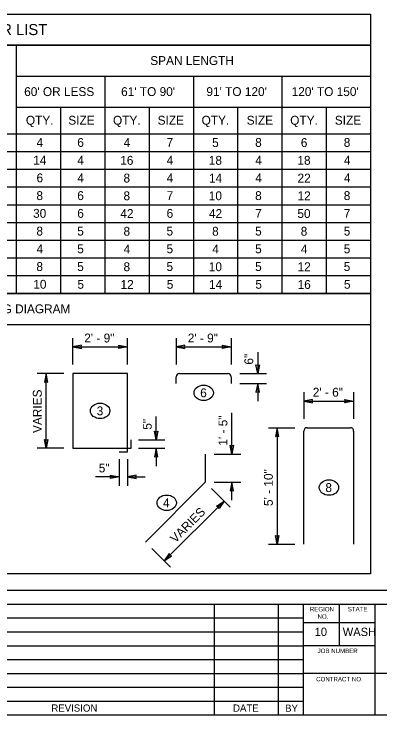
# Model space of a CAD drawing. Extents: x 99862 to 103151, y 100000 to 102076.
# Drawn here: x 100566 to 101227, y 100000 to 101265 of the extents above; entities that cross this region are included whole.
import ezdxf

# ---------------------------------------------------------------- set-up
doc = ezdxf.new("R2010")
doc.units = 0
for name, color, linetype in [('Level 10', 7, 'Continuous'), ('Level 15', 7, 'Continuous'), ('Level 20', 7, 'Continuous'), ('Level 40', 7, 'Continuous'), ('Level 60', 7, 'Continuous')]:
    doc.layers.add(name, color=color, linetype=linetype)

msp = doc.modelspace()

# ---------------------------------------------------------------- linework, layer by layer
at = {"layer": 'Level 10'}
for p, q in [((100864.8, 100616.2), (100951.8, 100616.2)), ((100864.8, 100616.2), (100951.8, 100616.2)), ((100858.8, 100598.2), (100858.8, 100610.2)), ((100858.8, 100598.2), (100858.8, 100610.2)), ((100957.8, 100610.2), (100957.8, 100598.2)), ((100957.8, 100610.2), (100957.8, 100598.2)), ((101095.1, 100518.4), (101173.1, 100518.4)), ((101089.1, 100308.4), (101089.1, 100512.4)), ((101179.1, 100512.4), (101179.1, 100308.4)), ((100911.1, 100470.9), (100911.1, 100419.9)), ((100911.1, 100470.9), (100911.1, 100419.9)), ((100911.1, 100419.9), (100803.1, 100311.9)), ((100911.1, 100419.9), (100803.1, 100311.9))]:
    msp.add_line(p, q, dxfattribs=at)
for points in [[(100770.8, 100474.7), (100770.8, 100616.2), (100671.8, 100616.2), (100671.8, 100481.2), (100777.4, 100481.2)], [(100770.8, 100474.7), (100770.8, 100616.2), (100671.8, 100616.2), (100671.8, 100481.2), (100777.4, 100481.2)], [(100777.4, 100481.2), (100777.4, 100496.2)], [(100777.4, 100481.2), (100777.4, 100496.2)], [(100755.8, 100474.7), (100770.8, 100474.7)], [(100755.8, 100474.7), (100770.8, 100474.7)]]:
    msp.add_lwpolyline(points, dxfattribs=at)
for centre, start, end in [((100864.8, 100610.2), 90, 180), ((100864.8, 100610.2), 90, 180), ((100951.8, 100610.2), 0, 90), ((100951.8, 100610.2), 0, 90), ((101095.1, 100512.4), 90, 180), ((101173.1, 100512.4), 0, 90)]:
    msp.add_arc(centre, 6, start, end, dxfattribs=at)
at = {"layer": 'Level 15'}
for p, q in [((100671.8, 100632.2), (100671.8, 100680.2)), ((100671.8, 100632.2), (100671.8, 100680.2)), ((100770.8, 100632.2), (100770.8, 100680.2)), ((100770.8, 100632.2), (100770.8, 100680.2)), ((100858.8, 100680.2), (100858.8, 100632.2)), ((100858.8, 100680.2), (100858.8, 100632.2)), ((100957.8, 100680.2), (100957.8, 100632.2)), ((100957.8, 100680.2), (100957.8, 100632.2)), ((100671.8, 100664.2), (100770.8, 100664.2)), ((100671.8, 100664.2), (100770.8, 100664.2)), ((100858.8, 100664.2), (100957.8, 100664.2)), ((100858.8, 100664.2), (100957.8, 100664.2)), ((101005.8, 100654.6), (101005.8, 100616.2)), ((101005.8, 100654.6), (101005.8, 100616.2)), ((100655.8, 100616.2), (100607.8, 100616.2)), ((100655.8, 100616.2), (100607.8, 100616.2)), ((100623.8, 100481.2), (100623.8, 100616.2)), ((100623.8, 100481.2), (100623.8, 100616.2)), ((100973.8, 100616.2), (101021.8, 100616.2)), ((100973.8, 100616.2), (101021.8, 100616.2)), ((100973.8, 100598.2), (101021.8, 100598.2)), ((100973.8, 100598.2), (101021.8, 100598.2)), ((101005.8, 100598.2), (101005.8, 100566.2)), ((101005.8, 100598.2), (101005.8, 100566.2)), ((101089.1, 100582.4), (101089.1, 100534.4)), ((101089.1, 100582.4), (101089.1, 100534.4)), ((101179.1, 100582.4), (101179.1, 100534.4)), ((101179.1, 100582.4), (101179.1, 100534.4)), ((101089.1, 100566.4), (101179.1, 100566.4)), ((101089.1, 100566.4), (101179.1, 100566.4)), ((100959.1, 100470.9), (100959.1, 100545.3)), ((100959.1, 100470.9), (100959.1, 100545.3)), ((100822.4, 100496.2), (100822.4, 100538.3)), ((100822.4, 100496.2), (100822.4, 100538.3)), ((101025.1, 100518.4), (101073.1, 100518.4)), ((101025.1, 100518.4), (101073.1, 100518.4)), ((101041.1, 100518.4), (101041.1, 100308.4)), ((100790.4, 100496.2), (100838.4, 100496.2)), ((100790.4, 100496.2), (100838.4, 100496.2)), ((100655.8, 100481.2), (100607.8, 100481.2)), ((100655.8, 100481.2), (100607.8, 100481.2)), ((100790.4, 100481.2), (100838.4, 100481.2)), ((100790.4, 100481.2), (100838.4, 100481.2)), ((100822.4, 100481.2), (100822.4, 100449.2)), ((100822.4, 100481.2), (100822.4, 100449.2)), ((100927.1, 100470.9), (100975.1, 100470.9)), ((100927.1, 100470.9), (100975.1, 100470.9)), ((100755.8, 100461.7), (100755.8, 100413.7)), ((100755.8, 100461.7), (100755.8, 100413.7)), ((100770.8, 100461.7), (100770.8, 100413.7)), ((100770.8, 100461.7), (100770.8, 100413.7)), ((100755.8, 100429.7), (100713.2, 100429.7)), ((100755.8, 100429.7), (100713.2, 100429.7)), ((100770.8, 100429.7), (100802.8, 100429.7)), ((100770.8, 100429.7), (100802.8, 100429.7)), ((100927.1, 100419.9), (100975.1, 100419.9)), ((100927.1, 100419.9), (100975.1, 100419.9)), ((100959.1, 100387.9), (100959.1, 100419.9)), ((100959.1, 100387.9), (100959.1, 100419.9)), ((100922.4, 100408.6), (100956.3, 100374.7)), ((100922.4, 100408.6), (100956.3, 100374.7)), ((100945, 100386), (100837, 100278)), ((100814.4, 100300.6), (100848.3, 100266.6)), ((100814.4, 100300.6), (100848.3, 100266.6)), ((101025.1, 100308.4), (101073.1, 100308.4)), ((101025.1, 100308.4), (101073.1, 100308.4))]:
    msp.add_line(p, q, dxfattribs=at)
for points in [[(100671.8, 100664.2), (100687.6, 100661.1), (100686.8, 100664.2), (100687.6, 100667.3)], [(100671.8, 100664.2), (100687.6, 100661.1), (100686.8, 100664.2), (100687.6, 100667.3)], [(100770.8, 100664.2), (100755.1, 100661.1), (100755.8, 100664.2), (100755.1, 100667.3)], [(100770.8, 100664.2), (100755.1, 100661.1), (100755.8, 100664.2), (100755.1, 100667.3)], [(100858.8, 100664.2), (100874.5, 100661.1), (100873.8, 100664.2), (100874.5, 100667.3)], [(100858.8, 100664.2), (100874.5, 100661.1), (100873.8, 100664.2), (100874.5, 100667.3)], [(100957.8, 100664.2), (100942.1, 100661.1), (100942.8, 100664.2), (100942.1, 100667.3)], [(100957.8, 100664.2), (100942.1, 100661.1), (100942.8, 100664.2), (100942.1, 100667.3)], [(101005.8, 100616.2), (101002.7, 100631.9), (101005.8, 100631.2), (101008.9, 100631.9)], [(101005.8, 100616.2), (101002.7, 100631.9), (101005.8, 100631.2), (101008.9, 100631.9)], [(100623.8, 100616.2), (100620.8, 100600.5), (100623.8, 100601.2), (100626.9, 100600.5)], [(100623.8, 100616.2), (100620.8, 100600.5), (100623.8, 100601.2), (100626.9, 100600.5)], [(101005.8, 100598.2), (101002.7, 100582.5), (101005.8, 100583.2), (101008.9, 100582.5)], [(101005.8, 100598.2), (101002.7, 100582.5), (101005.8, 100583.2), (101008.9, 100582.5)], [(101089.1, 100566.4), (101104.8, 100563.3), (101104.1, 100566.4), (101104.8, 100569.5)], [(101089.1, 100566.4), (101104.8, 100563.3), (101104.1, 100566.4), (101104.8, 100569.5)], [(101179.1, 100566.4), (101163.4, 100563.3), (101164.1, 100566.4), (101163.4, 100569.5)], [(101179.1, 100566.4), (101163.4, 100563.3), (101164.1, 100566.4), (101163.4, 100569.5)], [(101041.1, 100518.4), (101038, 100502.6), (101041.1, 100503.4), (101044.2, 100502.6)], [(101041.1, 100518.4), (101038, 100502.6), (101041.1, 100503.4), (101044.2, 100502.6)], [(100822.4, 100496.2), (100819.3, 100511.9), (100822.4, 100511.2), (100825.5, 100511.9)], [(100822.4, 100496.2), (100819.3, 100511.9), (100822.4, 100511.2), (100825.5, 100511.9)], [(100623.8, 100481.2), (100620.8, 100496.9), (100623.8, 100496.2), (100626.9, 100496.9)], [(100623.8, 100481.2), (100620.8, 100496.9), (100623.8, 100496.2), (100626.9, 100496.9)], [(100822.4, 100481.2), (100819.3, 100465.5), (100822.4, 100466.2), (100825.5, 100465.5)], [(100822.4, 100481.2), (100819.3, 100465.5), (100822.4, 100466.2), (100825.5, 100465.5)], [(100959.1, 100470.9), (100956, 100486.6), (100959.1, 100485.9), (100962.2, 100486.6)], [(100959.1, 100470.9), (100956, 100486.6), (100959.1, 100485.9), (100962.2, 100486.6)], [(100755.8, 100429.7), (100740.1, 100426.6), (100740.8, 100429.7), (100740.1, 100432.7)], [(100755.8, 100429.7), (100740.1, 100426.6), (100740.8, 100429.7), (100740.1, 100432.7)], [(100770.8, 100429.7), (100786.6, 100426.6), (100785.8, 100429.7), (100786.6, 100432.7)], [(100770.8, 100429.7), (100786.6, 100426.6), (100785.8, 100429.7), (100786.6, 100432.7)], [(100959.1, 100419.9), (100956, 100404.2), (100959.1, 100404.9), (100962.2, 100404.2)], [(100959.1, 100419.9), (100956, 100404.2), (100959.1, 100404.9), (100962.2, 100404.2)], [(100945, 100386), (100936.1, 100372.7), (100934.4, 100375.4), (100931.7, 100377)], [(100945, 100386), (100936.1, 100372.7), (100934.4, 100375.4), (100931.7, 100377)], [(101041.1, 100308.4), (101038, 100324.1), (101041.1, 100323.4), (101044.2, 100324.1)], [(101041.1, 100308.4), (101038, 100324.1), (101041.1, 100323.4), (101044.2, 100324.1)], [(100837, 100278), (100850.3, 100286.9), (100847.6, 100288.6), (100846, 100291.3)], [(100837, 100278), (100850.3, 100286.9), (100847.6, 100288.6), (100846, 100291.3)]]:
    msp.add_lwpolyline(points, close=True, dxfattribs=at)
at = {"layer": 'Level 20'}
for centre in [(100908.3, 100581.3), (100721.3, 100548.7), (101134.5, 100410.4), (100841.5, 100382.9), (100841.5, 100382.9)]:
    msp.add_ellipse(centre, major_axis=(-17.5, 0), ratio=0.8, dxfattribs=at)
at = {"layer": 'Level 40'}
for p, q in [((101209.6, 101264.8), (101209.6, 101208.8)), ((101209.6, 101264.8), (101209.6, 101208.8)), ((100569.6, 101208.8), (100569.6, 100760.8)), ((100569.6, 101208.8), (101209.6, 101208.8)), ((100569.6, 101208.8), (100569.6, 100760.8)), ((100569.6, 101208.8), (101209.6, 101208.8)), ((100569.6, 101152.8), (101209.6, 101152.8)), ((100569.6, 101152.8), (101209.6, 101152.8)), ((100729.6, 101152.8), (100729.6, 100760.8)), ((100729.6, 101152.8), (100729.6, 100760.8)), ((100889.6, 101152.8), (100889.6, 100760.8)), ((100889.6, 101152.8), (100889.6, 100760.8)), ((101049.6, 101152.8), (101049.6, 100760.8)), ((101049.6, 101152.8), (101049.6, 100760.8)), ((100569.6, 101096.8), (101209.6, 101096.8)), ((100569.6, 101096.8), (101209.6, 101096.8)), ((100649.6, 101096.8), (100649.6, 100760.8)), ((100649.6, 101096.8), (100649.6, 100760.8)), ((100809.6, 101096.8), (100809.6, 100760.8)), ((100809.6, 101096.8), (100809.6, 100760.8)), ((100969.6, 101096.8), (100969.6, 100760.8)), ((100969.6, 101096.8), (100969.6, 100760.8)), ((101129.6, 101096.8), (101129.6, 100760.8)), ((101129.6, 101096.8), (101129.6, 100760.8)), ((100017.1, 101048.8), (101209.6, 101048.8)), ((100017.1, 101048.8), (101209.6, 101048.8)), ((100121.1, 101016.8), (101209.6, 101016.8)), ((100121.1, 101016.8), (101209.6, 101016.8)), ((100121.1, 100984.8), (101209.6, 100984.8)), ((100121.1, 100984.8), (101209.6, 100984.8)), ((100121.1, 100952.8), (101209.6, 100952.8)), ((100121.1, 100952.8), (101209.6, 100952.8)), ((100121.1, 100920.8), (101209.6, 100920.8)), ((100121.1, 100920.8), (101209.6, 100920.8)), ((100121.1, 100888.8), (101209.6, 100888.8)), ((100121.1, 100888.8), (101209.6, 100888.8)), ((100121.1, 100856.8), (101209.6, 100856.8)), ((100121.1, 100856.8), (101209.6, 100856.8)), ((100017.1, 100824.8), (101209.6, 100824.8)), ((100017.1, 100824.8), (101209.6, 100824.8)), ((100017.1, 100792.8), (101209.6, 100792.8)), ((100017.1, 100704.8), (101209.6, 100704.8)), ((100017.1, 100704.8), (101209.6, 100704.8))]:
    msp.add_line(p, q, dxfattribs=at)
msp.add_lwpolyline([(101209.6, 101208.8), (100017.1, 101208.8), (100017.1, 101264.8), (101209.6, 101264.8)], dxfattribs=at)
msp.add_lwpolyline([(101209.6, 101208.8), (100017.1, 101208.8), (100017.1, 101264.8), (101209.6, 101264.8)], dxfattribs=at)
for points in [[(100017.1, 101208.8), (101209.6, 101208.8), (101209.6, 100760.8), (100017.1, 100760.8)], [(100017.1, 101208.8), (101209.6, 101208.8), (101209.6, 100760.8), (100017.1, 100760.8)], [(100017.1, 100254.8), (100017.1, 100760.8), (101209.6, 100760.8), (101209.6, 100254.8)]]:
    msp.add_lwpolyline(points, close=True, dxfattribs=at)
at = {"layer": 'Level 60'}
for p, q in [((100000, 100225), (103150, 100225)), ((100000, 100200), (101490.1, 100200)), ((100927.5, 100200), (100927.5, 100000)), ((101042.5, 100200), (101042.5, 100000)), ((101088.1, 100200), (101088.1, 100000)), ((101153.5, 100125), (101153.5, 100200)), ((101218.1, 100000), (101218.1, 100200)), ((100436.1, 100175), (101088.5, 100175)), ((101218.2, 100166.1), (101088.5, 100166.1)), ((100436.1, 100150), (101088.5, 100150)), ((100000, 100125), (101088.5, 100125)), ((101218.2, 100125), (101088.5, 100125)), ((100000, 100100), (101088.5, 100100)), ((100000, 100075), (101088.5, 100075)), ((101490.1, 100075), (101088.5, 100075)), ((100000, 100050), (101088.5, 100050)), ((100000, 100025), (101088.5, 100025)), ((100000, 100000), (103150, 100000))]:
    msp.add_line(p, q, dxfattribs=at)

# ---------------------------------------------------------------- texts
at = {"layer": 'Level 20'}
for s, height, p in [('BAR LIST', 20, (100507, 101226.8)), ('BAR LIST', 20, (100507, 101226.8)), ('SPAN LENGTH', 16, (100811.8, 101172.8)), ('SPAN LENGTH', 16, (100811.8, 101172.8)), ("60' OR LESS", 16, (100584.1, 101116.8)), ("60' OR LESS", 16, (100584.1, 101116.8)), ("61' TO 90'", 16, (100759.2, 101116.8)), ("61' TO 90'", 16, (100759.2, 101116.8)), ("91' TO 120'", 16, (100913.1, 101116.8)), ("91' TO 120'", 16, (100913.1, 101116.8)), ("120' TO 150'", 16, (101067.1, 101116.8)), ("120' TO 150'", 16, (101067.1, 101116.8)), ('QTY.', 16, (100587.2, 101065.1)), ('QTY.', 16, (100587.2, 101065.1)), ('SIZE', 16, (100663.8, 101065.1)), ('SIZE', 16, (100663.8, 101065.1)), ('QTY.', 16, (100744.5, 101065.1)), ('QTY.', 16, (100744.5, 101065.1)), ('SIZE', 16, (100825.1, 101065.1)), ('SIZE', 16, (100825.1, 101065.1)), ('QTY.', 16, (100904.5, 101065.1)), ('QTY.', 16, (100904.5, 101065.1)), ('SIZE', 16, (100986, 101065.1)), ('SIZE', 16, (100986, 101065.1)), ('QTY.', 16, (101064.5, 101065.1)), ('QTY.', 16, (101064.5, 101065.1)), ('SIZE', 16, (101145.1, 101065.1)), ('SIZE', 16, (101145.1, 101065.1)), ('4', 16, (100606.5, 101025.1)), ('6', 16, (100680, 101025.1)), ('4', 16, (100763.8, 101024.8)), ('7', 16, (100841.3, 101025.1)), ('5', 16, (100923.5, 101024.8)), ('8', 16, (101001.2, 101025.1)), ('6', 16, (101083.7, 101024.8)), ('8', 16, (101161.2, 101025.1)), ('14', 16, (100600.5, 100993.1)), ('4', 16, (100680.2, 100993.1)), ('16', 16, (100757.6, 100992.8)), ('4', 16, (100841.5, 100993.1)), ('18', 16, (100917.5, 100992.8)), ('4', 16, (101001.5, 100993.1)), ('18', 16, (101077.5, 100992.8)), ('4', 16, (101161.5, 100993.1)), ('6', 16, (100606.4, 100961.1)), ('4', 16, (100680.2, 100961.1)), ('8', 16, (100763.5, 100960.8)), ('4', 16, (100841.5, 100961.1)), ('14', 16, (100917.8, 100960.8)), ('4', 16, (101001.5, 100961.1)), ('22', 16, (101077.8, 100960.8)), ('4', 16, (101161.5, 100961.1)), ('8', 16, (100606.2, 100929.1)), ('6', 16, (100680, 100929.1)), ('8', 16, (100763.5, 100928.8)), ('7', 16, (100841.3, 100929.1)), ('10', 16, (100917.5, 100928.8)), ('8', 16, (101001.2, 100929.1)), ('12', 16, (101077.8, 100928.8)), ('8', 16, (101161.2, 100929.1)), ('30', 16, (100600.2, 100897.1)), ('6', 16, (100680, 100897.1)), ('42', 16, (100757.8, 100896.8)), ('6', 16, (100841.3, 100897.1)), ('42', 16, (100917.8, 100896.8)), ('7', 16, (101001.3, 100897.1)), ('50', 16, (101077.5, 100896.8)), ('7', 16, (101161.3, 100897.1)), ('8', 16, (100606.2, 100865.1)), ('5', 16, (100679.9, 100865.1)), ('8', 16, (100763.5, 100864.8)), ('5', 16, (100841.2, 100865.1)), ('8', 16, (100923.5, 100864.8)), ('5', 16, (101001.2, 100865.1)), ('8', 16, (101083.5, 100864.8)), ('5', 16, (101161.2, 100865.1)), ('4', 16, (100606.5, 100833.1)), ('5', 16, (100679.9, 100833.1)), ('4', 16, (100763.8, 100832.8)), ('5', 16, (100841.2, 100833.1)), ('4', 16, (100923.8, 100832.8)), ('5', 16, (101001.2, 100833.1)), ('4', 16, (101083.8, 100832.8)), ('5', 16, (101161.2, 100833.1)), ('8', 16, (100606.2, 100801.1)), ('5', 16, (100679.9, 100801.1)), ('5', 16, (100679.9, 100801.1)), ('8', 16, (100763.5, 100800.8)), ('5', 16, (100841.2, 100801.1)), ('10', 16, (100917.5, 100800.8)), ('5', 16, (101001.2, 100801.1)), ('12', 16, (101077.8, 100800.8)), ('5', 16, (101161.2, 100801.1)), ('10', 16, (100600.6, 100769.1)), ('5', 16, (100680.3, 100769.1)), ('12', 16, (100758.1, 100768.8)), ('5', 16, (100841.6, 100769.1)), ('14', 16, (100917.9, 100768.8)), ('5', 16, (101001.6, 100769.1)), ('16', 16, (101077.9, 100768.8)), ('5', 16, (101161.6, 100769.1)), ('BENDING DIAGRAM', 16, (100464.3, 100724.8)), ('2\' - 9"', 16, (100692.6, 100672.2)), ('2\' - 9"', 16, (100879.5, 100672.2)), ('2\' - 6"', 16, (101105.3, 100574.4)), ('6', 16, (100902, 100573.3)), ('3', 16, (100715.1, 100540.7)), ('8', 16, (101128.1, 100402.4)), ('4', 16, (100834.8, 100374.9)), ('4', 16, (100834.8, 100374.9))]:
    msp.add_text(s, height=height, dxfattribs=at).set_placement(p)
for s, rotation, p in [('6"', 90, (100997.8, 100632.2)), ('VARIES', 90, (100615.8, 100508.8)), ('5"', 90, (100814.4, 100514.7)), ('1\' - 5"', 90, (100951.1, 100485.9)), ('5"', 360, (100718.8, 100437.7)), ('5"', 360, (100718.8, 100437.7)), ('5\' - 10"', 90, (101033.1, 100377)), ('5\' - 10"', 90, (101033.1, 100377)), ('VARIES', 45, (100857.2, 100309.4))]:
    msp.add_text(s, height=16, rotation=rotation, dxfattribs=at).set_placement(p)
at = {"layer": 'Level 60'}
for s, height, p in [('REGION', 8, (101100, 100186.9)), ('STATE', 8, (101168.5, 100187)), ('NO.', 8, (101113.9, 100173.7)), ('10', 15, (101108.7, 100142.5)), ('WASH', 15, (101159.4, 100142.5)), ('JOB NUMBER', 8, (101114, 100111.7)), ('CONTRACT NO.', 8, (101111.4, 100060.7)), ('REVISION', 13, (100633.2, 100006)), ('DATE', 13, (100961.3, 100006)), ('BY', 13, (101055.3, 100005.7))]:
    msp.add_text(s, height=height, dxfattribs=at).set_placement(p)

doc.saveas('drawing.dxf')
